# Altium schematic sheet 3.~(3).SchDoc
size 420 x 297 mm
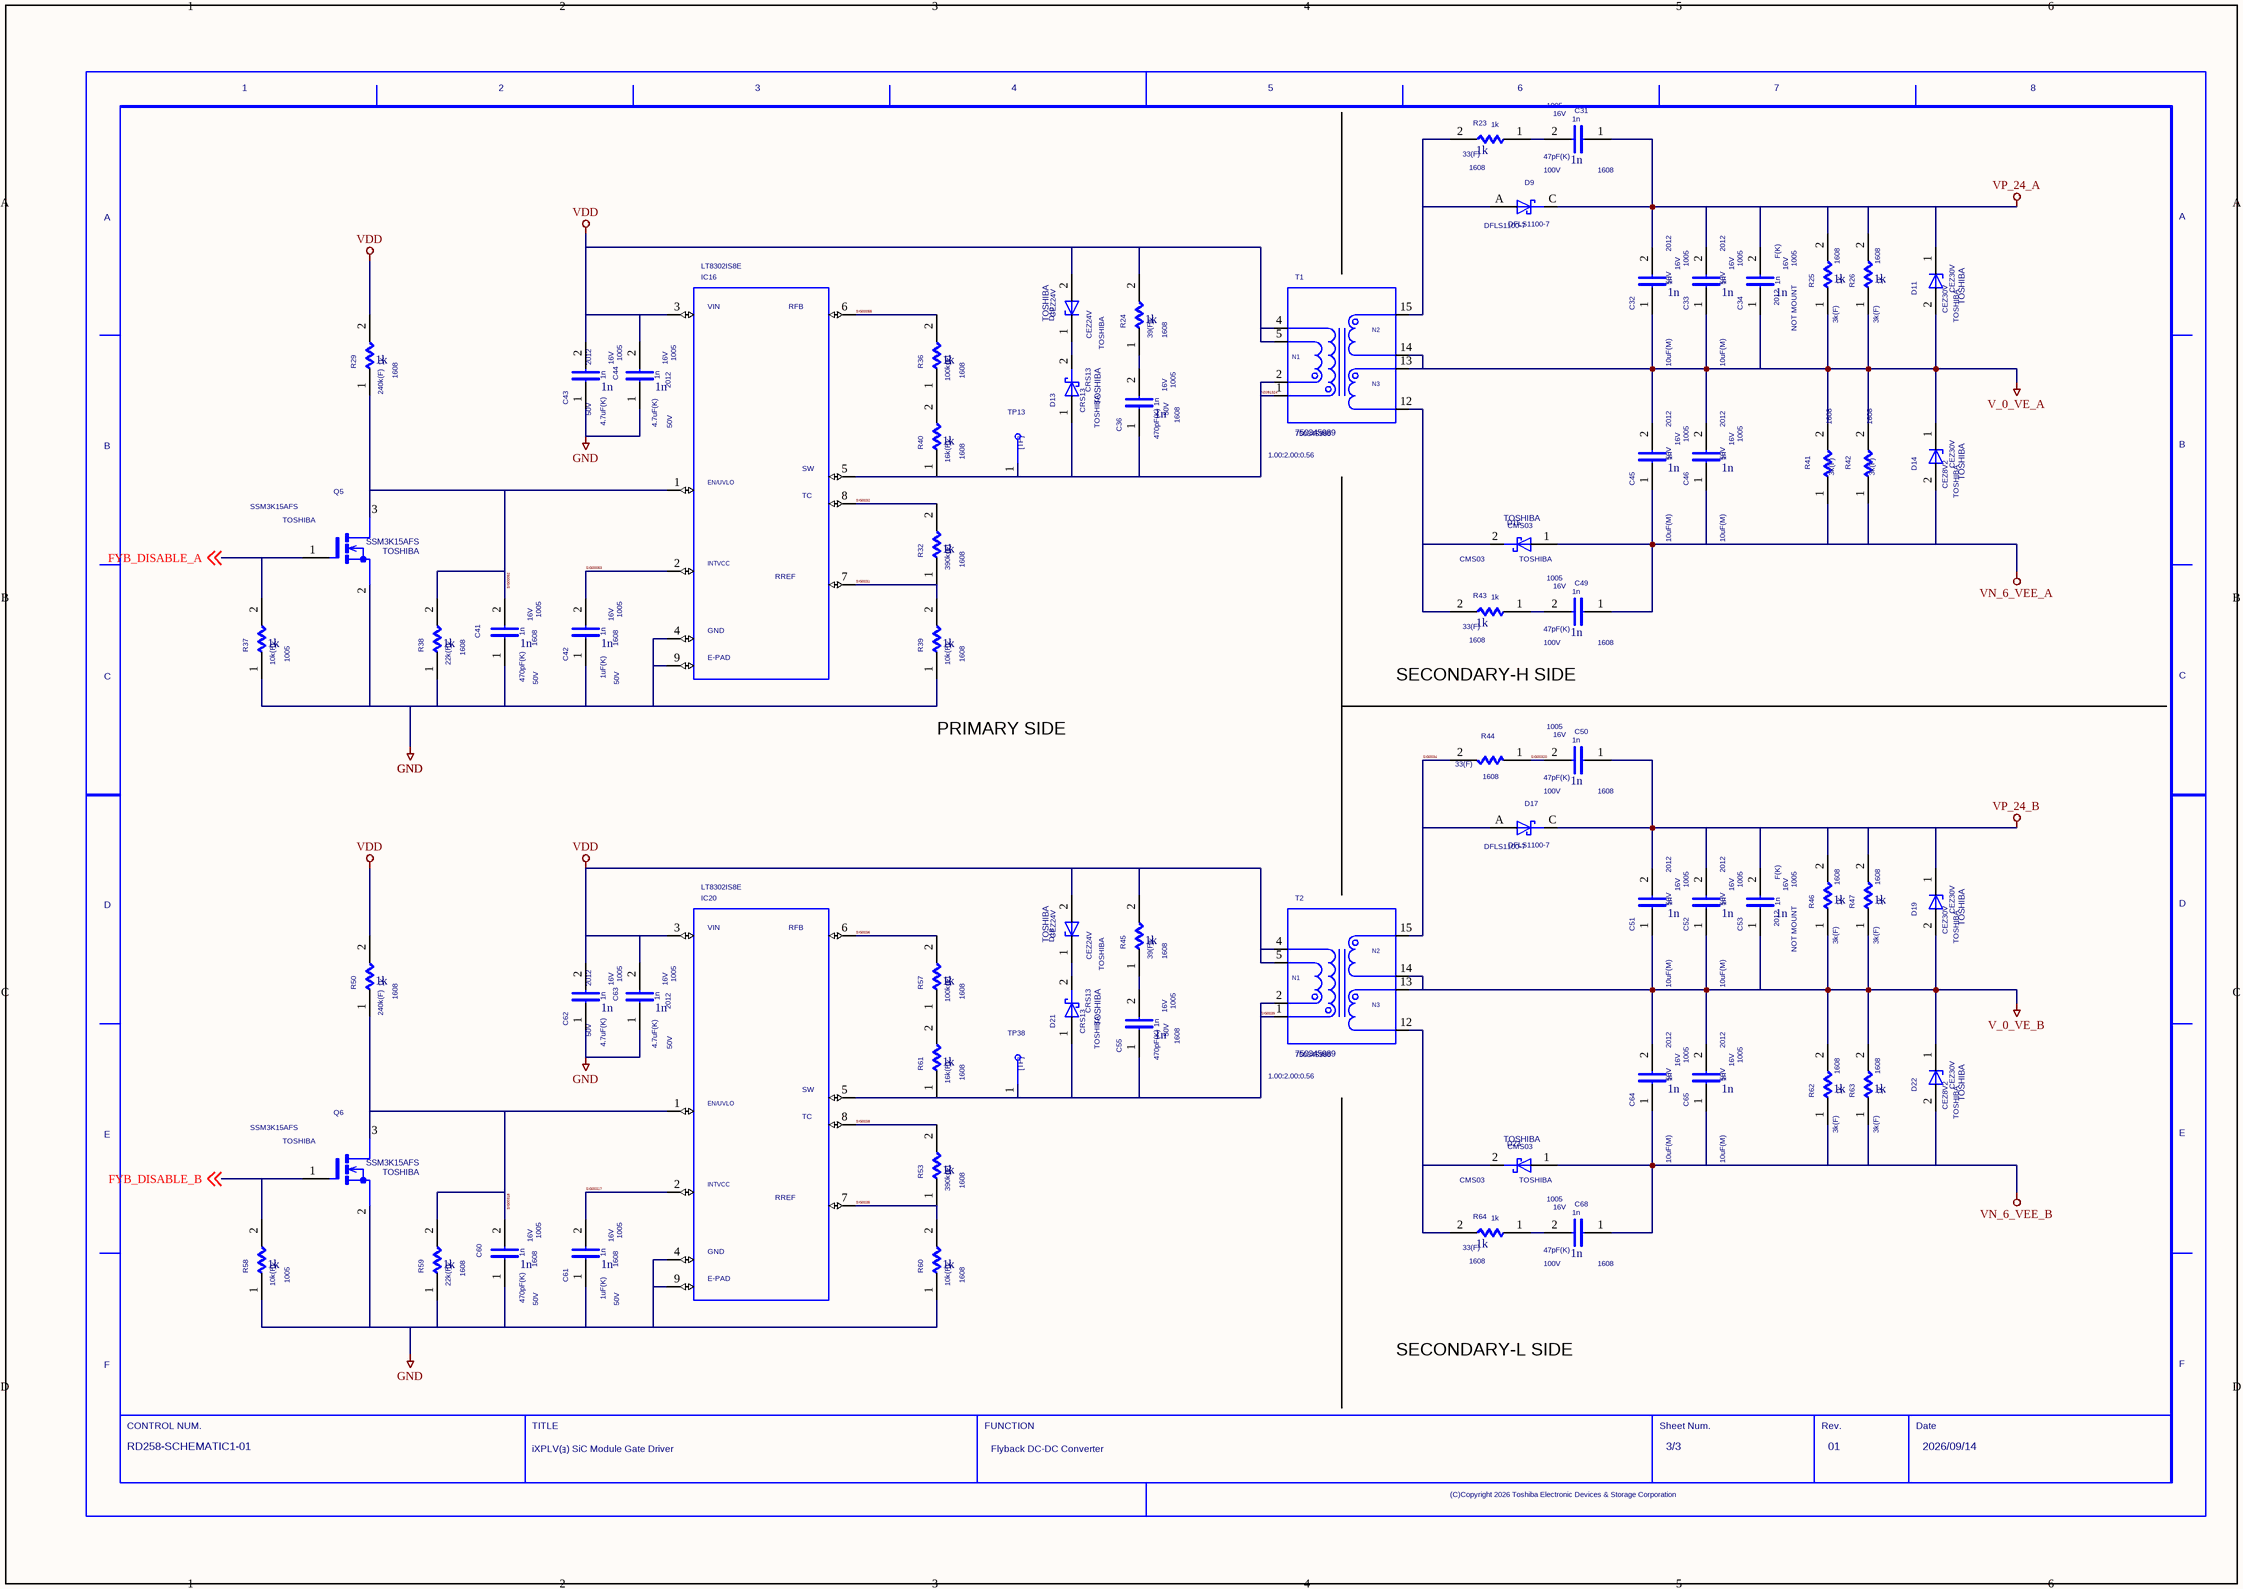
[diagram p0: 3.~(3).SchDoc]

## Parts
C31  1n  VAL1: 47pF(K)  SIZE: 1005  VOLTAGE: 16V  SIZECODESMD: 1608  VAL2: 100V
C32  1n  VAL1: 10uF(M)  SIZE: 1005  VOLTAGE: 16V  SIZECODESMD: 2012  VAL2: 50V
C33  1n  VAL1: 10uF(M)  SIZE: 1005  VOLTAGE: 16V  SIZECODESMD: 2012  VAL2: 50V
C34  1n  VAL1: F(K)  SIZE: 1005  VOLTAGE: 16V  NOTMOUNT: NOT MOUNT  SIZECODESMD: 2012
C36  1n  VAL1: 470pF(K)  SIZE: 1005  VOLTAGE: 16V  SIZECODESMD: 1608  VAL2: 50V
C41  1n  VAL1: 470pF(K)  SIZE: 1005  VOLTAGE: 16V  SIZECODESMD: 1608  VAL2: 50V
C42  1n  VAL1: 1uF(K)  SIZE: 1005  VOLTAGE: 16V  SIZECODESMD: 1608  VAL2: 50V
C43  1n  VAL1: 4.7uF(K)  SIZE: 1005  VOLTAGE: 16V  SIZECODESMD: 2012  VAL2: 50V
C44  1n  VAL1: 4.7uF(K)  SIZE: 1005  VOLTAGE: 16V  SIZECODESMD: 2012  VAL2: 50V
C45  1n  VAL1: 10uF(M)  SIZE: 1005  VOLTAGE: 16V  SIZECODESMD: 2012  VAL2: 50V
C46  1n  VAL1: 10uF(M)  SIZE: 1005  VOLTAGE: 16V  SIZECODESMD: 2012  VAL2: 50V
C49  1n  VAL1: 47pF(K)  SIZE: 1005  VOLTAGE: 16V  SIZECODESMD: 1608  VAL2: 100V
C50  1n  VAL1: 47pF(K)  SIZE: 1005  VOLTAGE: 16V  SIZECODESMD: 1608  VAL2: 100V
C51  1n  VAL1: 10uF(M)  SIZE: 1005  VOLTAGE: 16V  SIZECODESMD: 2012  VAL2: 50V
C52  1n  VAL1: 10uF(M)  SIZE: 1005  VOLTAGE: 16V  SIZECODESMD: 2012  VAL2: 50V
C53  1n  VAL1: F(K)  SIZE: 1005  VOLTAGE: 16V  NOTMOUNT: NOT MOUNT  SIZECODESMD: 2012
C55  1n  VAL1: 470pF(K)  SIZE: 1005  VOLTAGE: 16V  SIZECODESMD: 1608  VAL2: 50V
C60  1n  VAL1: 470pF(K)  SIZE: 1005  VOLTAGE: 16V  SIZECODESMD: 1608  VAL2: 50V
C61  1n  VAL1: 1uF(K)  SIZE: 1005  VOLTAGE: 16V  SIZECODESMD: 1608  VAL2: 50V
C62  1n  VAL1: 4.7uF(K)  SIZE: 1005  VOLTAGE: 16V  SIZECODESMD: 2012  VAL2: 50V
C63  1n  VAL1: 4.7uF(K)  SIZE: 1005  VOLTAGE: 16V  SIZECODESMD: 2012  VAL2: 50V
C64  1n  VAL1: 10uF(M)  SIZE: 1005  VOLTAGE: 16V  SIZECODESMD: 2012  VAL2: 50V
C65  1n  VAL1: 10uF(M)  SIZE: 1005  VOLTAGE: 16V  SIZECODESMD: 2012  VAL2: 50V
C68  1n  VAL1: 47pF(K)  SIZE: 1005  VOLTAGE: 16V  SIZECODESMD: 1608  VAL2: 100V
D9  DFLS1100-7
D10  CEZ24V  VENDOR: TOSHIBA
D11  CEZ30V  VENDOR: TOSHIBA
D13  CRS13  VENDOR: TOSHIBA
D14  CEZ30V  VENDOR: TOSHIBA  VAL3: CEZ8V2
D15  CMS03  VENDOR: TOSHIBA
D17  DFLS1100-7
D18  CEZ24V  VENDOR: TOSHIBA
D19  CEZ30V  VENDOR: TOSHIBA
D21  CRS13  VENDOR: TOSHIBA
D22  CEZ30V  VENDOR: TOSHIBA  VAL3: CEZ8V2
D23  CMS03  VENDOR: TOSHIBA
IC16  LT8302IS8E
IC20  LT8302IS8E
Q5  SSM3K15AFS  VENDOR: TOSHIBA
Q6  SSM3K15AFS  VENDOR: TOSHIBA
R23  1k  VAL1: 33(F)  SIZECODESMD: 1608
R24  1k  VAL1: 39(F)  SIZECODESMD: 1608
R25  1k  VAL1: 3k(F)  SIZECODESMD: 1608
R26  1k  VAL1: 3k(F)  SIZECODESMD: 1608
R29  1k  VAL1: 240k(F)  SIZECODESMD: 1608
R32  1k  VAL1: 390k(F)  SIZECODESMD: 1608
R36  1k  VAL1: 100k(F)  SIZECODESMD: 1608
R37  1k  VAL1: 10k(F)  SIZECODESMD: 1005
R38  1k  VAL1: 22k(F)  SIZECODESMD: 1608
R39  1k  VAL1: 10k(F)  SIZECODESMD: 1608
R40  1k  VAL1: 16k(F)  SIZECODESMD: 1608
R41  VAL1: 3k(F)  SIZECODESMD: 1608  (hidden comment: R)
R42  VAL1: 3k(F)  SIZECODESMD: 1608  (hidden comment: R)
R43  1k  VAL1: 33(F)  SIZECODESMD: 1608
R44  VAL1: 33(F)  SIZECODESMD: 1608  (hidden comment: R)
R45  1k  VAL1: 39(F)  SIZECODESMD: 1608
R46  1k  VAL1: 3k(F)  SIZECODESMD: 1608
R47  1k  VAL1: 3k(F)  SIZECODESMD: 1608
R50  1k  VAL1: 240k(F)  SIZECODESMD: 1608
R53  1k  VAL1: 390k(F)  SIZECODESMD: 1608
R57  1k  VAL1: 100k(F)  SIZECODESMD: 1608
R58  1k  VAL1: 10k(F)  SIZECODESMD: 1005
R59  1k  VAL1: 22k(F)  SIZECODESMD: 1608
R60  1k  VAL1: 10k(F)  SIZECODESMD: 1608
R61  1k  VAL1: 16k(F)  SIZECODESMD: 1608
R62  1k  VAL1: 3k(F)  SIZECODESMD: 1608
R63  1k  VAL1: 3k(F)  SIZECODESMD: 1608
R64  1k  VAL1: 33(F)  SIZECODESMD: 1608
T1  750345989  VAL1: 1.00:2.00:0.56
T2  750345989  VAL1: 1.00:2.00:0.56
TP13  TP  (value not drawn)
TP38  TP  (value not drawn)
U?  DATE: 2026/09/14  DRAWINGNUMBER: RD258-SCHEMATIC1-01  TITLE: iXPLV(ｮ) SiC Module Gate Driver  FUNCTION: Flyback DC-DC Converter  SHEETNUMBER: 3/3  REVISION: 01  (hidden comment: WAKU_DEF100)

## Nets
GND: C41.1 C42.1 C43.1 C44.1 C60.1 C61.1 C62.1 C63.1 IC16.4 IC16.9 IC20.4 IC20.9 Q5.2(S) Q6.2(S) R37.1 R38.1 R39.1 R58.1 R59.1 R60.1
V_0_VE_A: C32.1 C33.1 C34.1 C45.2 C46.2 D11.2(A) D14.1(C) R25.1 R26.1 R41.2 R42.2 T1.13 T1.14
V_0_VE_B: C51.1 C52.1 C53.1 C64.2 C65.2 D19.2(A) D22.1(C) R46.1 R47.1 R62.2 R63.2 T2.13 T2.14
VDD: C43.2 C44.2 C62.2 C63.2 D10.2(A) D18.2(A) IC16.3 IC20.3 R24.2 R29.2 R45.2 R50.2 T1.4 T1.5 T2.4 T2.5
VN_6_VEE_A: C45.1 C46.1 C49.1 D14.2(A) D15.1(A) R41.1 R42.1
VN_6_VEE_B: C64.1 C65.1 C68.1 D22.2(A) D23.1(A) R62.1 R63.1
VP_24_A: C31.1 C32.2 C33.2 C34.2 D9.C D11.1(C) R25.2 R26.2
VP_24_B: C50.1 C51.2 C52.2 C53.2 D17.C D19.1(C) R46.2 R47.2
FYB_DISABLE_A: Q5.1(G) R37.2 ; off-sheet FYB_DISABLE_A
FYB_DISABLE_B: Q6.1(G) R58.2 ; off-sheet FYB_DISABLE_B
N2091324: C36.1 D13.1(A) IC16.5 R40.1 T1.1 T1.2 TP13.1
SIG0031: IC16.7 R32.1 R39.2
SIG0032: IC16.8 R32.2
SIG0033: C49.2 R43.1
SIG0034: D17.A R44.2 T2.15
SIG0035: IC20.7 R53.1 R60.2
SIG0036: IC20.6 R57.2
SIG0037: C68.2 R64.1
SIG0038: IC20.8 R53.2
SIG0039: C55.1 D21.1(A) IC20.5 R61.1 T2.1 T2.2 TP38.1
SIG00040: D10.1(C) D13.2(C)
SIG00041: C36.2 R24.1
SIG00042: D9.A R23.2 T1.15
SIG00043: C31.2 R23.1
SIG00050: D15.2(C) R43.2 T1.12
SIG00052: C41.2 IC16.1 Q5.3(D) R29.1 R38.2
SIG00053: C42.2 IC16.2
SIG00055: IC16.6 R36.2
SIG00310: D23.2(C) R64.2 T2.12
SIG00311: C55.2 R45.1
SIG00312: D18.1(C) D21.2(C)
SIG00317: C61.2 IC20.2
SIG00318: C60.2 IC20.1 Q6.3(D) R50.1 R59.2
SIG00320: C50.2 R44.1
NetR36_1: R36.1 R40.2
NetR57_1: R57.1 R61.2

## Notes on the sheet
- SECONDARY-H SIDE
- PRIMARY SIDE
- SECONDARY-L SIDE

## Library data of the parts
C31 C49 C50 C68 = C: TIME: 11:55:01; UPDATEUSER: HP_Z8_KEYSHOT; SAVECOUNT: 2; TC1: 0; PSPICETEMPLATE: C^@REFDES %1 %2 ?TOLERANCE¦C^@REFDES¦ @VALUE ?IC/IC=@IC/ TC=@TC1,@TC2 ?TOLERANCE¦\n.model C^@REFDES CAP C=1 DEV=@TOLERANCE% TC1=@TC1 TC2=@TC2 VC1=@VC1 VC2=@VC2¦; ORIGINALSYMBOLORIGIN: (0,0); INSTANCENAME: INS2090890
C32-C34 C45 C46 C51-C53 C64 C65 = C: TIME: 11:55:01; UPDATEUSER: HP_Z8_KEYSHOT; SAVECOUNT: 2; TC1: 0; PSPICETEMPLATE: C^@REFDES %1 %2 ?TOLERANCE¦C^@REFDES¦ @VALUE ?IC/IC=@IC/ TC=@TC1,@TC2 ?TOLERANCE¦\n.model C^@REFDES CAP C=1 DEV=@TOLERANCE% TC1=@TC1 TC2=@TC2 VC1=@VC1 VC2=@VC2¦; ORIGINALSYMBOLORIGIN: (0,0); INSTANCENAME: INS2091140
C36 C44 C55 C63 = C: TIME: 11:55:01; UPDATEUSER: HP_Z8_KEYSHOT; SAVECOUNT: 2; TC1: 0; PSPICETEMPLATE: C^@REFDES %1 %2 ?TOLERANCE¦C^@REFDES¦ @VALUE ?IC/IC=@IC/ TC=@TC1,@TC2 ?TOLERANCE¦\n.model C^@REFDES CAP C=1 DEV=@TOLERANCE% TC1=@TC1 TC2=@TC2 VC1=@VC1 VC2=@VC2¦; ORIGINALSYMBOLORIGIN: (0,0); INSTANCENAME: INS2091518
C41 C42 C60 C61 = C: TIME: 11:55:01; UPDATEUSER: HP_Z8_KEYSHOT; SAVECOUNT: 2; TC1: 0; PSPICETEMPLATE: C^@REFDES %1 %2 ?TOLERANCE¦C^@REFDES¦ @VALUE ?IC/IC=@IC/ TC=@TC1,@TC2 ?TOLERANCE¦\n.model C^@REFDES CAP C=1 DEV=@TOLERANCE% TC1=@TC1 TC2=@TC2 VC1=@VC1 VC2=@VC2¦; ORIGINALSYMBOLORIGIN: (0,0); INSTANCENAME: INS2092186
C43 C62 = C: TIME: 11:55:01; UPDATEUSER: HP_Z8_KEYSHOT; SAVECOUNT: 2; TC1: 0; PSPICETEMPLATE: C^@REFDES %1 %2 ?TOLERANCE¦C^@REFDES¦ @VALUE ?IC/IC=@IC/ TC=@TC1,@TC2 ?TOLERANCE¦\n.model C^@REFDES CAP C=1 DEV=@TOLERANCE% TC1=@TC1 TC2=@TC2 VC1=@VC1 VC2=@VC2¦; ORIGINALSYMBOLORIGIN: (0,0); INSTANCENAME: INS2092266
D9 D17 = DFLS1100: TIME: 14:49:55; UPDATEUSER: fukuda-y; UPDATETIME: 08:18:42; SAVECOUNT: 6; SAVEAREA0: -4630,-153,17114,13055; PSPICETEMPLATE: X^@REFDES %C %A @MODEL; ORIGINALSYMBOLORIGIN: (0,0); INSTANCENAME: INS2090946
D10 D18 = CEZ24V: TIME: 14:49:55; UPDATEUSER: fukuda-y; UPDATETIME: 08:18:42; SAVECOUNT: 6; SAVEAREA0: -4630,-153,17114,13055; PSPICETEMPLATE: X^@REFDES %A %C @MODEL; ORIGINALSYMBOLORIGIN: (0,0); INSTANCENAME: INS2091294
D11 D14 D19 D22 = CEZ30V: TIME: 14:49:55; UPDATEUSER: fukuda-y; UPDATETIME: 08:18:42; SAVECOUNT: 6; SAVEAREA0: -4630,-153,17114,13055; PSPICETEMPLATE: X^@REFDES %C %A @MODEL; ORIGINALSYMBOLORIGIN: (0,0); INSTANCENAME: INS2091274
D13 D21 = CRS13: TIME: 14:49:55; UPDATEUSER: fukuda-y; UPDATETIME: 08:18:42; SAVECOUNT: 6; SAVEAREA0: -4630,-153,17114,13055; PSPICETEMPLATE: X^@REFDES %A %C @MODEL; ORIGINALSYMBOLORIGIN: (0,0); INSTANCENAME: INS2091426
D15 D23 = CMS03: TIME: 14:49:55; UPDATEUSER: fukuda-y; UPDATETIME: 08:16:22; SAVECOUNT: 9; SAVEAREA0: -4630,-153,17114,13055; PSPICETEMPLATE: X^@REFDES %A %C @MODEL; ORIGINALSYMBOLORIGIN: (0,0); INSTANCENAME: INS2091824
IC16 IC20 = LT8302: TIME: 11:55:00; UPDATEUSER: t5459927; UPDATETIME: 18:09:57; SAVECOUNT: 8; PSPICETEMPLATE: X^@REFDES %EN/UVLO %INTVCC %VIN %GND %SW %RFB %RREF %TC %EXPOSED_PAD @MODEL; OriginalSymbolOrigin: (0,0); INSTANCENAME: INS2091844
Q5 Q6 = SSM3K15AFS: TIME: 11:54:59; UPDATEUSER: HP_Z8_KEYSHOT; UPDATETIME: 11:55:00; SAVECOUNT: 2; ORIGINALSYMBOLORIGIN: (0,0); PSPICETEMPLATE: X^@REFDES %D %G %S @MODEL; INSTANCENAME: INS2091762
R23 R43 R64 = R_Dup1: TIME: 11:54:58; UPDATEUSER: HP_Z8_KEYSHOT; UPDATETIME: 11:54:59; SAVECOUNT: 2; WATT: 0.125; COMP: R; TC1: 0; PSPICETEMPLATE: R^@REFDES %1 %2 ?TOLERANCE¦R^@REFDES¦ @VALUE TC=@TC1,@TC2 ?TOLERANCE¦\n.model R^@REFDES RES R=1 DEV=@TOLERANCE% TC1=@TC1 TC2=@TC2¦; ORIGINALSYMBOLORIGIN: (0,0); VAL2: 100mW; INSTANCENAME: INS2090866
R24 R29 R32 R36-R40 R45 R50 R53 R57-R61 = R_Dup1: TIME: 11:54:58; UPDATEUSER: HP_Z8_KEYSHOT; UPDATETIME: 11:54:59; SAVECOUNT: 2; WATT: 0.125; COMP: R; TC1: 0; PSPICETEMPLATE: R^@REFDES %1 %2 ?TOLERANCE¦R^@REFDES¦ @VALUE TC=@TC1,@TC2 ?TOLERANCE¦\n.model R^@REFDES RES R=1 DEV=@TOLERANCE% TC1=@TC1 TC2=@TC2¦; ORIGINALSYMBOLORIGIN: (0,0); VAL2: 100mW; INSTANCENAME: INS2091678
R25 R26 R46 R47 R62 R63 = R_Dup1: TIME: 11:54:58; UPDATEUSER: HP_Z8_KEYSHOT; UPDATETIME: 11:54:59; SAVECOUNT: 2; WATT: 0.125; COMP: R; TC1: 0; PSPICETEMPLATE: R^@REFDES %1 %2 ?TOLERANCE¦R^@REFDES¦ @VALUE TC=@TC1,@TC2 ?TOLERANCE¦\n.model R^@REFDES RES R=1 DEV=@TOLERANCE% TC1=@TC1 TC2=@TC2¦; ORIGINALSYMBOLORIGIN: (0,0); VAL2: 100mW; INSTANCENAME: INS2091226
R41 R42 R44 = R: VAL2: 100mW; OriginalSymbolOrigin: (5080,5080); SAVECOUNT: 0
T1 T2 = 750345989_2: TIME: 11:55:02; UPDATEUSER: t5459927; UPDATETIME: 19:39:05; SAVECOUNT: 3; PSPICETEMPLATE: X^@REFDES %1 %2 %3 %4 %5 %6 %7 %8 @MODEL; OriginalSymbolOrigin: (0,0); INSTANCENAME: INS2101815
TP13 TP38 = TP: TIME: 16:12:21; UPDATEUSER: fukuda-y; UPDATETIME: 16:18:11; SAVECOUNT: 2; SAVEAREA0: -242,-92,12810,7836; ORIGINALSYMBOLORIGIN: (0,0); INSTANCENAME: INS2091728
U? = WAKU_DEF100: PLOTTIME: HH:MM; SAVEAREA0: -63393,-16950,474261,314592; TIME: 14:30:25; UPDATEUSER: d5009410; UPDATETIME: 15:37:05; SAVECOUNT: 4; OriginalSymbolOrigin: (10160,284480); SHTSAVECOUNT: 40; NUMBER DEVICES IN PACKAGE: 1; SHEET NUM: X/X; PIN NUMBERS VISIBLE: False; CONTROL NUM: RD256-SCHEMATIC-0; PIN NAMES ROTATE: True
